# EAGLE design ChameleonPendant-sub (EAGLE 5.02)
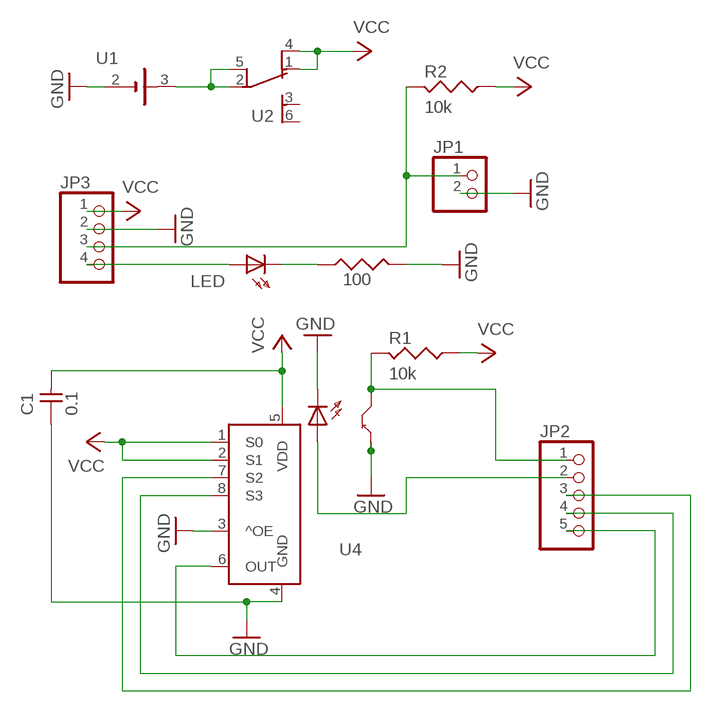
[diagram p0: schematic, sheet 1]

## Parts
C1  0.1  1608  [1608]
JP1  PINHD-1X2SMD  [1X02-SMD]
JP2  PINHD-1X5  [1X05]
JP3  PINHD-1X4  [1X04]
LED  LED3MM  [LED3MM]
R1  10k  1608  [1608]
R2  10k  1608  [1608]
R_W2  100  1608  [1608]
U1  2032SLIM2  [CR2032SLIM2]
U2  0_SWITCHMICRO  [0_SLIDEMICRO]
U3  TCS230  [TCS230]
U4  GP2S40  [GP2S40]

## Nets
GND: C1.P$1 JP1.2 JP3.2 R_W2.2 U1.2(-) U3.3(^OE) U3.4(GND) U4.2(DIODE_E) U4.4(LED_C)
N$1: JP2.3 U3.7(S2)
N$2: JP2.4 U3.8(S3)
N$3: U1.3(+) U2.2(P) U2.5(P1)
N$4: JP2.1 R1.2 U4.3(DIODE_C)
N$19: JP1.1 JP3.3 R2.2
N$21: LED.K(C) R_W2.1
N$23: JP2.2 U4.1(LED_A)
N$25: JP3.4 LED.A
N$29: JP2.5 U3.6(OUT)
VCC: C1.P$2 JP3.1 R1.1 R2.1 U2.1(O) U2.4(O1) U3.1(S0) U3.2(S1) U3.5(VDD)
Unconnected: U2.3(S) U2.6(S1)

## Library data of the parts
C1 = 01_capacitor:1608
JP1 = 09_con-pin:PINHD-1X2: PIN HEADER
JP2 = 09_con-pin:PINHD-1X5: PIN HEADER
JP3 = 09_con-pin:PINHD-1X4: PIN HEADER
LED = 06_led:LED: LED
R1 R2 R_W2 = 02_resistor:1608
U1 = 00_other-parts:2032SLIM
U2 = 08_switch-other:0_SWITCHMICRO
U3 = 00_other-parts:TCS230
U4 = 00_other-parts:GP2S40

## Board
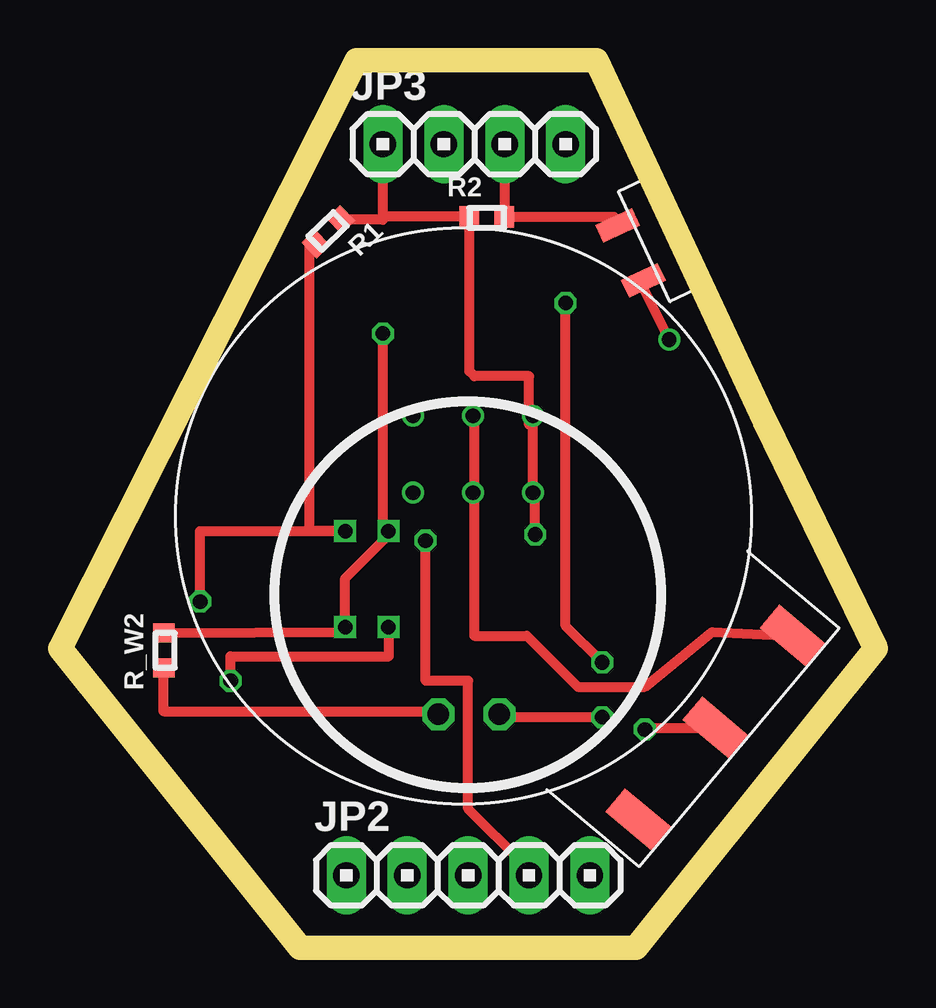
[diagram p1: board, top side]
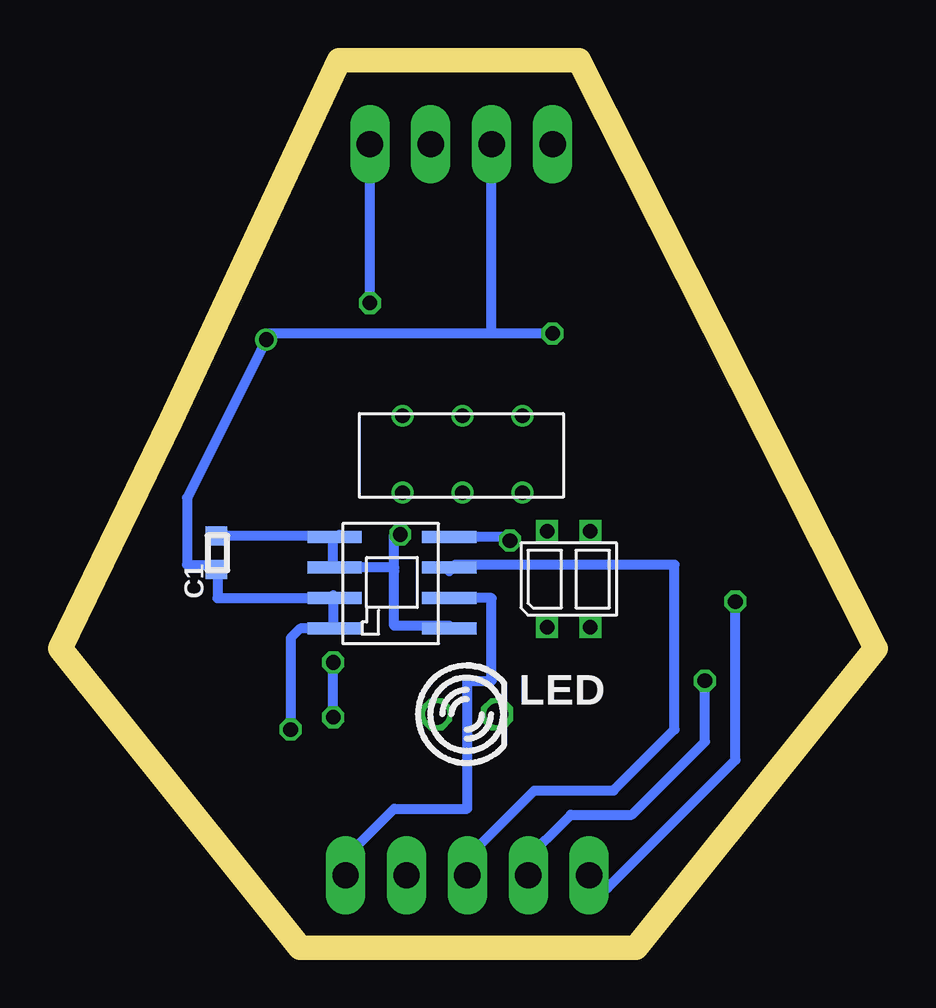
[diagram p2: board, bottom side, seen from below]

Size 34 x 37 mm. Coordinates in mm from the lower left corner, seen from the top.
Outline: 29.37,22 22.37,37 12.37,37 0,12.47 10,0 24,0 34,12.47 29.37,22
Copper layers (1*16): Top 0.035mm / dielectric 1.5mm / Bottom 0.035mm
Design rules "p-ban_min": minimum track width 0.15mm, minimum drill 0.6mm, track to track 0.15mm, track to pad 0.15mm, pad to pad 0.15mm, via to via 0.15mm, smd to smd 0.15mm, copper to edge 0.7mm, drill to drill 0.45mm, minimum pad ring 0.15mm, minimum via ring 0.15mm, stop-mask expansion 4mil, vias tented up to drill 0mil, thermal gap 0.15mm

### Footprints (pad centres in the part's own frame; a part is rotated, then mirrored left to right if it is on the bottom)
1608 = smd 0.8 x 0.9: P$1 -0.7,0.1; P$2 0.7,0.1
1X02-SMD = smd 0.813 x 1.676: 1 -1.27,0; 2 1.27,0
1X05 = drill 1.092 long: 1 -5.08,0; 2 -2.54,0; 3 0,0; 4 2.54,0; 5 5.08,0
1X04 = drill 1.092 long: 1 -3.81,0; 2 -1.27,0; 3 1.27,0; 4 3.81,0
LED3MM = drill 0.889 octagon: A -1.27,0; K 1.27,0
1608' = smd 0.8 x 0.9: 1 -0.715,0.037; 2 0.739,0.037
CR2032SLIM2 = smd 1.27 x 2.54: 1 -5,-13.73; 2 0,-13.73; 3 5,-13.73
0_SLIDEMICRO = drill 0.61 round: 1 -2.7,1.9; 2 -0.2,1.9; 3 2.3,1.9; 4 -2.7,-1.3; 5 -0.2,-1.3; 6 2.3,-1.3
TCS230 = smd 2.26 x 0.5: 1 -2.44,1.94; 2 -2.44,0.67; 3 -2.44,-0.6; 4 -2.44,-1.87; 5 2.34,-1.87; 6 2.34,-0.6; 7 2.34,0.67; 8 2.34,1.94
GP2S40 = drill 0.61 square: 1 -0.9,-2; 2 0.9,-2; 3 0.9,2; 4 -0.9,2

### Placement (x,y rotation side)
C1  27.38,16.46 90 bottom
JP1  23.79,28.96 295 top
JP2  17.02,3.01 0 top
JP3  17.27,33.49 0 top
LED  17.04,9.73 0 bottom
R1  10k  [1608']  11.17,29.87 224 top
R2  10k  [1608']  17.78,30.43 0 top
R_W2  100  [1608']  4.37,12.38 90 top
U1  16.82,17.99 50 top
U2  17.02,20.27 0 bottom
U3  20.11,15.17 0 bottom
U4  12.79,15.36 0 bottom

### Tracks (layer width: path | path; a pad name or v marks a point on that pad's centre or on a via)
GND  (via drill 0.61)
  Top 0.406: U1.2 24.64,9.16 v24.38,9.09 | JP1.2 24.13,27.89 v25.4,25.35 | R_W2.2 11.94,13.15 U4.2 11.89,15.39 13.72,17.22 13.69,17.24 U4.4 13.46,17.36 v13.46,25.6
  Bottom 0.406: 22.61,13.3 22.61,13.41 | v24.38,9.09 24.38,12.9 23.98,13.3 22.61,13.3 | 22.61,14.57 22.61,14.68 | 22.61,14.57 U3.3 27.43,14.57 27.43,15.76 | 22.61,13.3 U3.4 | 22.61,14.57 22.61,13.3 | 27.43,15.76 27.43,15.95 28.7,15.95 28.7,18.74 v25.4,25.35 25.4,25.6 16,25.6 | 27.43,15.76 C1.P$1 | 16,25.6 JP3.2 | v13.46,25.6 16,25.6
N$1
  Bottom 0.406: JP2.3 17.02,3.76 14.22,6.55 10.92,6.55 8.38,9.09 8.38,15.95 17.53,15.95 17.77,15.7 | 17.77,15.7 17.78,15.69 | 17.77,15.7 U3.7
N$2  (via drill 0.61)
  Top 0.406: v15.24,16.96 15.24,11.12 17.02,11.12 17.02,5.79 19.3,3.5 19.3,3.25 19.54,3.01 JP2.4
  Bottom 0.406: U3.8 15.24,17.11 v15.24,16.96
N$3
  Top 0.406: 17.27,18.97 U2.5 | U1.3 27.18,13.15 24.38,10.87 21.59,10.87 19.46,12.99 17.27,12.99 17.27,18.97 | 17.27,22.17 17.27,22.3 | 17.27,22.17 U2.2 | 17.27,18.97 17.27,22.17
N$4  (via drill 0.61)
  Top 0.406: R1.2 10.41,29.33 10.41,17.36 U4.3 5.84,17.36 v5.84,14.42
  Bottom 0.406: v5.84,14.42 5.84,7.82 11.18,2.49 11.68,2.49 11.94,2.74 JP2.1
N$19
  Top 0.406: 23.11,30.11 23.11,29.92 | 23.11,30.11 JP1.1 | 23.11,30.11 23.11,30.46 R2.2 18.54,30.46 | 18.54,30.46 18.54,30.43 | 18.54,30.46 JP3.3
N$21
  Top 0.406: R_W2.1 4.32,9.85 15.75,9.85 LED.K
N$23  (via drill 0.61)
  Top 0.406: U4.1 13.72,13.36 13.72,12.14 7.11,12.14 v7.11,11.12
  Bottom 0.406: v7.11,11.12 7.11,8.58 10.16,5.53 12.7,5.53 14.73,3.5 14.73,3.25 14.48,2.99 JP2.2
N$25  (via drill 0.61)
  Top 0.406: v21.08,26.87 21.08,13.41 v22.61,11.88 | LED.A 18.29,9.73 18.29,9.6 v22.61,9.6
  Bottom 0.406: v21.08,26.87 JP3.4 | v22.61,9.6 v22.61,11.88
N$29
  Bottom 0.406: U3.6 16,14.57 16,11.12 17.02,11.12 17.02,5.79 20.07,5.79 22.35,3.5 22.35,2.99 22.34,3.01 JP2.5
VCC  (via drill 0.61)
  Top 0.406: 13.46,33.73 JP3.1 13.46,30.43 | R1.1 13.46,30.34 13.46,30.43 | 13.46,30.43 13.46,30.46 R2.1 17.07,24.03 17.27,23.82 19.56,23.82 19.56,21.79 19.72,21.95 | 19.72,22.04 U2.1 | 19.72,21.95 19.72,22.04 | 19.72,22.04 19.81,22.04 19.72,21.95 | 19.72,21.95 U2.4 19.81,18.97 v19.81,17.22
  Bottom 0.406: C1.P$2 22.61,17.16 22.61,17.11 | 22.61,17.11 U3.1 | 22.61,16.96 22.61,15.84 U3.2 20.07,15.84 20.07,15.69 | 22.61,16.96 22.61,17.11 | 22.61,16.96 22.35,17.22 | 20.07,15.69 20.07,13.41 17.78,13.41 U3.5 | v19.81,17.22 20.07,17.22 20.07,15.69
